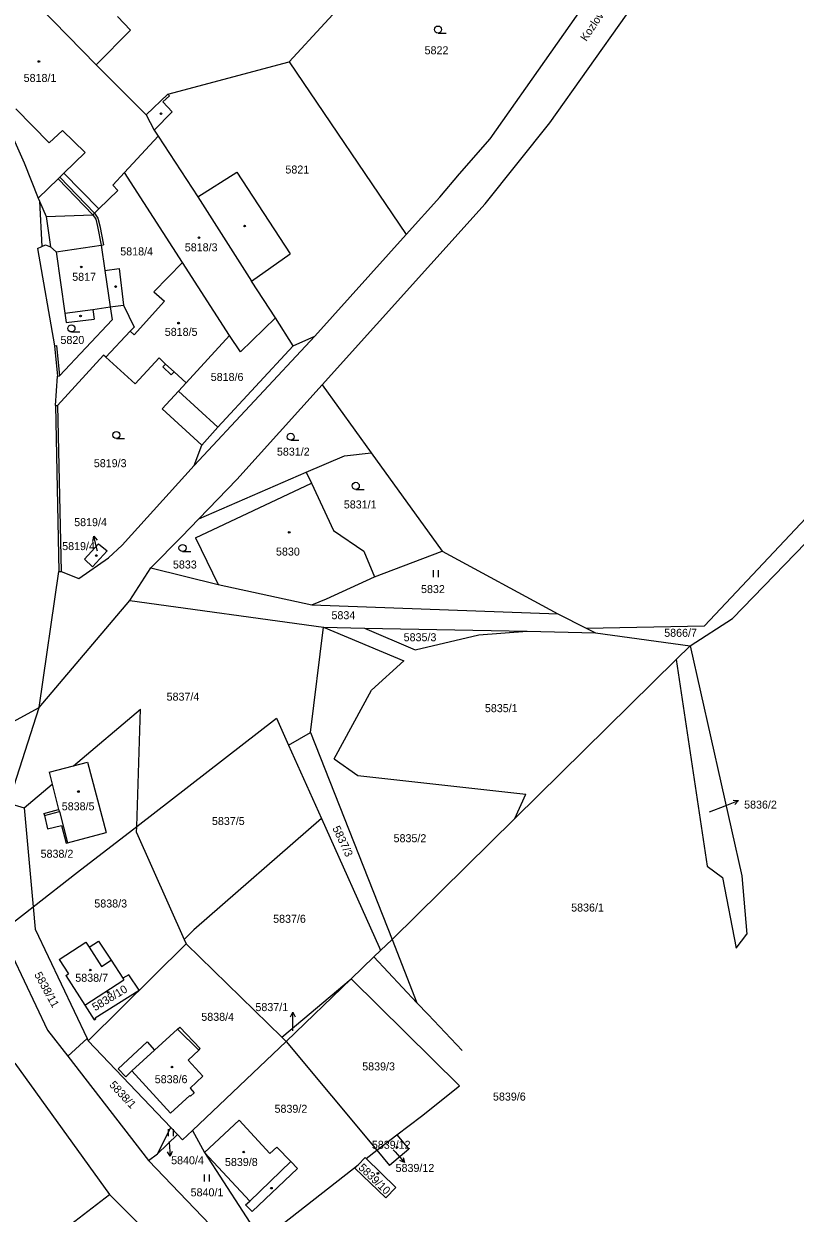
# Model space of a CAD drawing. Extents: x -717507 to -715515, y -957700 to -954941.
# Drawn here: x -715850.3 to -715686.5, y -955475.1 to -955222.4 of the extents above; entities that cross this region are included whole.
import ezdxf

# ---------------------------------------------------------------- set-up
doc = ezdxf.new("R2010")
doc.units = 0
for name, color, linetype in [('Hranice parcel', 7, 'Continuous'), ('Parcelní čísla', 7, 'Continuous'), ('Pop  PČ popisy', 7, 'Continuous'), ('Vnitřní kresba', 7, 'Continuous'), ('Značky budov', 7, 'Continuous'), ('Značky kultur', 7, 'Continuous')]:
    doc.layers.add(name, color=color, linetype=linetype)

msp = doc.modelspace()

# ---------------------------------------------------------------- linework, layer by layer
at = {"layer": 'Hranice parcel'}
for points in [[(-715738.6, -955243.39), (-715665.35, -955140.11)], [(-715793.97, -955230.46), (-715771.23, -955205.7)], [(-715751.32, -955246.77), (-715725.4, -955209.9)], [(-715853.12, -955212.39), (-715834.93, -955231.09)], [(-715834.93, -955231.09), (-715824.34, -955241.7)], [(-715819.71, -955237.33), (-715793.97, -955230.46)], [(-715793.97, -955230.46), (-715769.13, -955267.15)], [(-715824.34, -955241.7), (-715819.71, -955237.33)], [(-715820.8, -955238.95), (-715819.42, -955237.64)], [(-715819.71, -955237.33), (-715819.42, -955237.64)], [(-715822.63, -955244.95), (-715818.85, -955241.07)], [(-715820.8, -955238.95), (-715818.85, -955241.07)], [(-715854.51, -955242.32), (-715850.25, -955251.87)], [(-715752.32, -955260.58), (-715738.6, -955243.39)], [(-715828.97, -955253.97), (-715821.78, -955246.26)], [(-715822.63, -955244.95), (-715821.78, -955246.26)], [(-715821.78, -955246.26), (-715813.38, -955259.14)], [(-715757.78, -955254.24), (-715751.32, -955246.77)], [(-715850.25, -955251.87), (-715847.25, -955259.39)], [(-715831.45, -955256.63), (-715828.97, -955253.97)], [(-715816.61, -955273.07), (-715828.97, -955253.97)], [(-715813.38, -955259.14), (-715805.11, -955253.86)], [(-715805.11, -955253.86), (-715793.78, -955271.22)], [(-715847.25, -955259.39), (-715843.02, -955255.3)], [(-715843.02, -955255.3), (-715835.67, -955262.95)], [(-715761.99, -955259.2), (-715757.78, -955254.24)], [(-715834.39, -955261.7), (-715830.35, -955257.75)], [(-715831.45, -955256.63), (-715830.35, -955257.75)], [(-715847.25, -955259.39), (-715846.96, -955260.05)], [(-715846.96, -955260.05), (-715846.52, -955269.68)], [(-715787, -955299.06), (-715752.32, -955260.58)], [(-715769.13, -955267.15), (-715761.99, -955259.2)], [(-715835.67, -955262.95), (-715835.31, -955262.6)], [(-715835.31, -955262.6), (-715834.39, -955261.7)], [(-715788.52, -955288.71), (-715769.13, -955267.15)], [(-715847.44, -955270.13), (-715846.52, -955269.68)], [(-715847.44, -955270.13), (-715843.8, -955290.75)], [(-715846.52, -955269.68), (-715845.75, -955269.3)], [(-715845.75, -955269.3), (-715844.68, -955269.74)], [(-715844.68, -955269.74), (-715843.48, -955270.81)], [(-715843.48, -955270.81), (-715833.89, -955269.41)], [(-715843.48, -955270.81), (-715841.61, -955283.86)], [(-715833.89, -955269.41), (-715833.11, -955274.78)], [(-715801.94, -955277.03), (-715793.78, -955271.22)], [(-715816.61, -955273.07), (-715822.7, -955279.34)], [(-715806.62, -955288.55), (-715816.61, -955273.07)], [(-715833.11, -955274.78), (-715830.08, -955274.36)], [(-715830.08, -955274.36), (-715829.15, -955282.12)], [(-715796.91, -955284.85), (-715801.94, -955277.03)], [(-715820.45, -955281.3), (-715826.89, -955288.42)], [(-715822.7, -955279.34), (-715820.45, -955281.3)], [(-715841.61, -955283.86), (-715841.33, -955285.83)], [(-715835.68, -955283.03), (-715831.99, -955282.52)], [(-715835.68, -955283.03), (-715835.39, -955285.11)], [(-715831.99, -955282.52), (-715831.59, -955285.23)], [(-715829.15, -955282.12), (-715826.92, -955286.8)], [(-715842.73, -955297.17), (-715831.59, -955285.23)], [(-715841.33, -955285.83), (-715835.39, -955285.11)], [(-715827.72, -955287.65), (-715826.92, -955286.8)], [(-715796.91, -955284.85), (-715804.34, -955292.08)], [(-715793.11, -955290.76), (-715796.91, -955284.85)], [(-715832.94, -955293.16), (-715827.72, -955287.65)], [(-715826.89, -955288.42), (-715827.72, -955287.65)], [(-715806.62, -955288.55), (-715815.86, -955298.65)], [(-715814.15, -955316.23), (-715788.52, -955288.71)], [(-715804.34, -955292.08), (-715806.62, -955288.55)], [(-715793.11, -955290.76), (-715788.52, -955288.71)], [(-715843.8, -955290.75), (-715843.19, -955297.21)], [(-715843.16, -955303.47), (-715833.37, -955292.76)], [(-715832.94, -955293.16), (-715833.37, -955292.76)], [(-715826.67, -955298.86), (-715832.94, -955293.16)], [(-715826.67, -955298.86), (-715821.61, -955293.36)], [(-715821.61, -955293.36), (-715820.22, -955294.64)], [(-715820.79, -955295.27), (-715820.22, -955294.64)], [(-715820.79, -955295.27), (-715819.01, -955296.91)], [(-715819.01, -955296.91), (-715818.43, -955296.28)], [(-715818.43, -955296.28), (-715815.86, -955298.65)], [(-715705.8, -955350.3), (-715654.8, -955296.1)], [(-715843.61, -955303.48), (-715843.19, -955297.21)], [(-715843.19, -955297.21), (-715842.73, -955297.17)], [(-715817.47, -955300.4), (-715815.86, -955298.65)], [(-715805.11, -955319.15), (-715787, -955299.06)], [(-715787, -955299.06), (-715776.55, -955313.53)], [(-715820.93, -955304.17), (-715817.47, -955300.4)], [(-715843.61, -955303.48), (-715843.16, -955303.47)], [(-715843.61, -955303.48), (-715842.87, -955338.72)], [(-715820.93, -955304.17), (-715812.55, -955311.91)], [(-715699.86, -955348.7), (-715657.74, -955305.22)], [(-715814.15, -955316.23), (-715812.55, -955311.91)], [(-715790.34, -955317.64), (-715782.25, -955314.14)], [(-715782.25, -955314.14), (-715776.55, -955313.53)], [(-715776.55, -955313.53), (-715761.46, -955334.42)], [(-715829.47, -955333.13), (-715814.15, -955316.23)], [(-715813.15, -955327.52), (-715790.34, -955317.64)], [(-715813.15, -955327.52), (-715805.11, -955319.15)], [(-715790.34, -955317.64), (-715789.24, -955319.98)], [(-715813.85, -955331.54), (-715789.24, -955319.98)], [(-715789.24, -955319.98), (-715784.53, -955329.99)], [(-715816.82, -955331.34), (-715813.15, -955327.52)], [(-715823.38, -955337.96), (-715816.82, -955331.34)], [(-715813.85, -955331.54), (-715809.07, -955341.5)], [(-715784.53, -955329.99), (-715778.09, -955334.43)], [(-715837.42, -955336.07), (-715834.44, -955332.87), (-715832.63, -955334.34), (-715835.71, -955337.71), (-715837.42, -955336.07)], [(-715832.32, -955335.84), (-715829.47, -955333.13)], [(-715778.09, -955334.43), (-715775.84, -955339.87)], [(-715775.84, -955339.87), (-715761.46, -955334.42)], [(-715761.46, -955334.42), (-715736.9, -955347.72)], [(-715838.65, -955340.22), (-715832.32, -955335.84)], [(-715847.04, -955367.61), (-715842.87, -955338.72)], [(-715842.87, -955338.72), (-715842.42, -955338.71)], [(-715842.42, -955338.71), (-715838.65, -955340.22)], [(-715827.79, -955344.89), (-715823.38, -955337.96)], [(-715823.38, -955337.96), (-715809.07, -955341.5)], [(-715786.05, -955344.52), (-715775.84, -955339.87)], [(-715809.07, -955341.5), (-715789.19, -955345.81)], [(-715847.04, -955367.61), (-715827.79, -955344.89)], [(-715827.79, -955344.89), (-715786.66, -955350.55)], [(-715789.19, -955345.81), (-715786.05, -955344.52)], [(-715789.19, -955345.81), (-715736.9, -955347.72)], [(-715736.9, -955347.72), (-715730.91, -955350.73)], [(-715708.83, -955354.55), (-715699.86, -955348.7)], [(-715789.45, -955372.95), (-715786.66, -955350.55)], [(-715786.66, -955350.55), (-715777.96, -955350.73)], [(-715786.66, -955350.55), (-715769.65, -955357.7)], [(-715777.96, -955350.73), (-715767.25, -955355.35)], [(-715777.96, -955350.73), (-715743.42, -955351.43)], [(-715767.25, -955355.35), (-715753.69, -955352.17)], [(-715753.69, -955352.17), (-715743.42, -955351.43)], [(-715743.42, -955351.43), (-715728.93, -955351.73)], [(-715730.91, -955350.73), (-715705.8, -955350.3)], [(-715730.91, -955350.73), (-715728.93, -955351.73)], [(-715728.93, -955351.73), (-715708.83, -955354.55)], [(-715711.76, -955357.44), (-715708.83, -955354.55)], [(-715708.83, -955354.55), (-715697.87, -955403.39)], [(-715746.04, -955391.2), (-715711.76, -955357.44)], [(-715711.76, -955357.44), (-715705.22, -955401.33)], [(-715776.46, -955363.95), (-715769.65, -955357.7)], [(-715784.44, -955378.55), (-715776.46, -955363.95)], [(-715864.69, -955377.18), (-715847.04, -955367.61)], [(-715853.56, -955387.91), (-715847.04, -955367.61)], [(-715839.78, -955380.04), (-715825.55, -955368)], [(-715826.33, -955392.87), (-715825.55, -955368)], [(-715826.33, -955392.87), (-715796.68, -955369.86)], [(-715796.68, -955369.86), (-715794.1, -955375.62)], [(-715794.1, -955375.62), (-715789.45, -955372.95)], [(-715789.45, -955372.95), (-715772.12, -955416.88)], [(-715794.1, -955375.62), (-715787.11, -955391.19)], [(-715844.94, -955381.39), (-715839.78, -955380.04)], [(-715839.78, -955380.04), (-715836.77, -955379.25)], [(-715836.77, -955379.25), (-715832.81, -955394.21)], [(-715784.44, -955378.55), (-715779.39, -955382.1)], [(-715844.94, -955381.39), (-715844.31, -955383.88)], [(-715779.39, -955382.1), (-715743.74, -955386.05)], [(-715850.25, -955388.9), (-715844.31, -955383.88)], [(-715844.31, -955383.88), (-715842.95, -955389.27)], [(-715853.56, -955387.91), (-715850.25, -955388.9)], [(-715746.04, -955391.2), (-715743.74, -955386.05)], [(-715850.25, -955388.9), (-715848.33, -955409.96)], [(-715846.05, -955390.14), (-715842.95, -955389.27)], [(-715846.05, -955390.14), (-715845.94, -955390.59)], [(-715845.94, -955390.59), (-715845.28, -955393.39)], [(-715845.28, -955393.39), (-715842.31, -955392.69)], [(-715842.31, -955392.69), (-715841.34, -955396.45)], [(-715838.9, -955402.62), (-715826.33, -955392.87)], [(-715826.37, -955394.17), (-715826.33, -955392.87)], [(-715787.11, -955391.19), (-715814.24, -955414.84)], [(-715787.11, -955391.19), (-715774.88, -955418.55)], [(-715772.12, -955416.88), (-715746.04, -955391.2)], [(-715841.03, -955396.35), (-715832.81, -955394.21)], [(-715826.37, -955394.17), (-715816.26, -955416.93)], [(-715841.34, -955396.45), (-715841.03, -955396.35)], [(-715848.33, -955409.96), (-715838.9, -955402.62)], [(-715705.22, -955401.33), (-715701.92, -955403.77)], [(-715701.92, -955403.77), (-715699.08, -955418.73)], [(-715697.87, -955403.39), (-715696.81, -955415.75)], [(-715853.5, -955413.99), (-715848.33, -955409.96)], [(-715848.33, -955409.96), (-715847.9, -955414.7)], [(-715847.9, -955414.7), (-715836.9, -955437.95)], [(-715814.24, -955414.84), (-715816.26, -955416.93)], [(-715842.79, -955421.18), (-715837.18, -955417.48)], [(-715837.18, -955417.48), (-715836.48, -955418.55)], [(-715836.67, -955438.44), (-715815.86, -955417.83)], [(-715836.48, -955418.55), (-715834.43, -955417.23)], [(-715834.43, -955417.23), (-715831.78, -955421.33)], [(-715816.26, -955416.93), (-715815.86, -955417.83)], [(-715815.86, -955417.83), (-715795.53, -955437.64)], [(-715774.58, -955419.24), (-715772.12, -955416.88)], [(-715699.08, -955418.73), (-715696.81, -955415.75)], [(-715852.73, -955420.44), (-715845.27, -955436.19)], [(-715780.84, -955425.27), (-715775.98, -955420.59)], [(-715775.98, -955420.59), (-715774.58, -955419.24)], [(-715775.98, -955420.59), (-715766.86, -955430.39)], [(-715774.88, -955418.55), (-715774.58, -955419.24)], [(-715842.79, -955421.18), (-715840.82, -955424.17)], [(-715831.78, -955421.33), (-715829.33, -955425.11)], [(-715841.42, -955424.55), (-715840.82, -955424.17)], [(-715841.42, -955424.55), (-715837.4, -955430.88)], [(-715837.4, -955430.88), (-715829.08, -955425.5)], [(-715828.01, -955424.4), (-715829.33, -955425.11)], [(-715829.33, -955425.11), (-715829.08, -955425.5)], [(-715825.84, -955427.68), (-715828.01, -955424.4)], [(-715795.53, -955437.64), (-715780.84, -955425.27)], [(-715794.6, -955438.55), (-715780.84, -955425.27)], [(-715780.84, -955425.27), (-715757.81, -955447.99)], [(-715835.19, -955433.58), (-715825.84, -955427.68)], [(-715837.4, -955430.88), (-715835.38, -955433.99)], [(-715766.86, -955430.39), (-715764.47, -955432.85)], [(-715764.47, -955432.85), (-715757.23, -955440.47)], [(-715835.38, -955433.99), (-715835.06, -955433.78)], [(-715835.06, -955433.78), (-715835.19, -955433.58)], [(-715822.58, -955440.42), (-715817.67, -955435.93)], [(-715817.67, -955435.93), (-715817.22, -955435.56)], [(-715817.22, -955435.56), (-715812.86, -955440.05)], [(-715845.27, -955436.19), (-715840.99, -955441.71)], [(-715840.99, -955441.71), (-715836.9, -955437.95)], [(-715836.9, -955437.95), (-715836.67, -955438.44)], [(-715836.67, -955438.44), (-715819.07, -955456.86)], [(-715795.53, -955437.64), (-715794.6, -955438.55)], [(-715830.27, -955444.39), (-715824.16, -955438.68)], [(-715824.16, -955438.68), (-715822.58, -955440.42)], [(-715815.45, -955442.52), (-715813.16, -955440.41)], [(-715814.53, -955457.48), (-715794.6, -955438.55)], [(-715813.16, -955440.41), (-715812.86, -955440.05)], [(-715794.6, -955438.55), (-715775.38, -955461.67)], [(-715852.21, -955443.2), (-715832.1, -955471.05)], [(-715840.99, -955441.71), (-715823.82, -955463.87)], [(-715815.45, -955442.52), (-715812.28, -955445.97)], [(-715830.27, -955444.39), (-715828.69, -955446.08)], [(-715828.69, -955446.08), (-715827.39, -955444.8)], [(-715827.39, -955444.8), (-715819.16, -955453.81)], [(-715815.02, -955448.49), (-715812.28, -955445.97)], [(-715815.02, -955448.49), (-715814.14, -955449.45)], [(-715765.89, -955454.42), (-715757.81, -955447.99)], [(-715819.16, -955453.81), (-715815.08, -955450.05)], [(-715815.08, -955450.05), (-715814.95, -955450.2)], [(-715814.95, -955450.2), (-715814.14, -955449.45)], [(-715811.97, -955462.17), (-715804.57, -955455.26)], [(-715804.57, -955455.26), (-715798.06, -955462.39)], [(-715771.13, -955458.42), (-715765.89, -955454.42)], [(-715821.91, -955462.45), (-715819.07, -955456.86)], [(-715821.91, -955462.45), (-715817.69, -955458.31)], [(-715819.07, -955456.86), (-715817.69, -955458.31)], [(-715817.69, -955458.31), (-715816.6, -955459.45)], [(-715816.6, -955459.45), (-715814.53, -955457.48)], [(-715814.53, -955457.48), (-715811.97, -955462.17)], [(-715775.38, -955461.67), (-715771.13, -955458.42)], [(-715771.13, -955458.42), (-715768.57, -955461.46), (-715772.65, -955464.9)], [(-715798.06, -955462.39), (-715796.62, -955461)], [(-715796.62, -955461), (-715793.64, -955464.1)], [(-715823.82, -955463.87), (-715821.91, -955462.45)], [(-715811.97, -955462.17), (-715802.36, -955472.48)], [(-715811.97, -955462.17), (-715799.84, -955480.85)], [(-715779.3, -955464.75), (-715777.86, -955463.25)], [(-715777.86, -955463.25), (-715777.65, -955463.45)], [(-715777.65, -955463.45), (-715775.38, -955461.67)], [(-715777.65, -955463.45), (-715771.33, -955469.57)], [(-715775.38, -955461.67), (-715772.65, -955464.9)], [(-715823.82, -955463.87), (-715794.5, -955494.51)], [(-715801.82, -955474.72), (-715792.23, -955465.57)], [(-715799.84, -955480.85), (-715779.3, -955464.75)], [(-715793.64, -955464.1), (-715792.23, -955465.57)], [(-715780.01, -955465.48), (-715779.3, -955464.75)], [(-715780.01, -955465.48), (-715773.44, -955471.79)], [(-715843.19, -955479.58), (-715832.1, -955471.05)], [(-715832.1, -955471.05), (-715808.03, -955495.19)], [(-715773.44, -955471.79), (-715771.33, -955469.57)], [(-715803.22, -955473.28), (-715802.36, -955472.48)], [(-715803.22, -955473.28), (-715801.82, -955474.72)]]:
    msp.add_lwpolyline(points, dxfattribs=at)
at = {"layer": 'Pop  PČ popisy'}
for points in [[(-715835.7, -955332.34), (-715835.46, -955331.25), (-715834.73, -955332.1)], [(-715834.73, -955334.16), (-715835.46, -955331.25)], [(-715834.67, -955334.38), (-715834.73, -955334.16)], [(-715701.36, -955388.48), (-715698.56, -955387.4)], [(-715699.67, -955387.29), (-715698.56, -955387.4), (-715699.31, -955388.23)], [(-715704.71, -955389.78), (-715701.36, -955388.48)], [(-715793.67, -955433.32), (-715793.17, -955432.32), (-715792.67, -955433.32)], [(-715793.17, -955435.32), (-715793.17, -955432.32)], [(-715793.17, -955436.31), (-715793.17, -955435.32)], [(-715819.49, -955459.8), (-715819.48, -955459.97)], [(-715819.48, -955459.97), (-715819.24, -955462.96)], [(-715818.82, -955461.92), (-715819.24, -955462.96), (-715819.82, -955462)], [(-715771.91, -955461.57), (-715771.47, -955462.05)], [(-715771.47, -955462.05), (-715769.46, -955464.28)], [(-715769.76, -955463.2), (-715769.46, -955464.28), (-715770.5, -955463.87)]]:
    msp.add_lwpolyline(points, dxfattribs=at)
at = {"layer": 'Vnitřní kresba'}
for points in [[(-715830.46, -955220.81), (-715827.68, -955223.71)], [(-715834.93, -955231.09), (-715827.68, -955223.71)], [(-715852, -955240.42), (-715844.94, -955247.68)], [(-715824.34, -955241.7), (-715822.63, -955244.95)], [(-715844.94, -955247.68), (-715842.14, -955245.01)], [(-715842.14, -955245.01), (-715837.31, -955249.74)], [(-715841.8, -955254.11), (-715837.31, -955249.74)], [(-715843.02, -955255.3), (-715842.67, -955254.98)], [(-715842.67, -955254.98), (-715841.8, -955254.11)], [(-715842.67, -955254.98), (-715835.31, -955262.6)], [(-715841.8, -955254.11), (-715834.39, -955261.7)], [(-715846.96, -955260.05), (-715845.6, -955263.32)], [(-715813.38, -955259.14), (-715801.94, -955277.03)], [(-715845.6, -955263.32), (-715835.67, -955262.95)], [(-715845.6, -955263.32), (-715844.68, -955269.74)], [(-715835.67, -955262.95), (-715835.05, -955263.85)], [(-715835.31, -955262.6), (-715834.6, -955263.65)], [(-715835.05, -955263.85), (-715834.65, -955265.42)], [(-715834.6, -955263.65), (-715834.16, -955265.31)], [(-715834.65, -955265.42), (-715833.89, -955269.41)], [(-715834.16, -955265.31), (-715833.39, -955269.34)], [(-715833.89, -955269.41), (-715833.39, -955269.34)], [(-715833.11, -955274.78), (-715831.99, -955282.52)], [(-715841.61, -955283.86), (-715835.68, -955283.03)], [(-715831.99, -955282.52), (-715829.15, -955282.12)], [(-715843.8, -955290.75), (-715843.35, -955290.7)], [(-715843.35, -955290.7), (-715842.73, -955297.17)], [(-715809.09, -955308.09), (-715793.11, -955290.76)], [(-715820.22, -955294.64), (-715818.43, -955296.28)], [(-715817.47, -955300.4), (-715809.09, -955308.09)], [(-715843.16, -955303.47), (-715842.42, -955338.71)], [(-715812.55, -955311.91), (-715809.09, -955308.09)], [(-715845.94, -955390.59), (-715842.77, -955389.7)], [(-715842.95, -955389.27), (-715842.77, -955389.7)], [(-715842.77, -955389.7), (-715841.03, -955396.35)], [(-715772.12, -955416.88), (-715766.86, -955430.39)], [(-715836.48, -955418.55), (-715833.83, -955422.66)], [(-715833.83, -955422.66), (-715831.78, -955421.33)], [(-715817.67, -955435.93), (-715813.16, -955440.41)], [(-715827.39, -955444.8), (-715822.58, -955440.42)], [(-715802.36, -955472.48), (-715793.64, -955464.1)]]:
    msp.add_lwpolyline(points, dxfattribs=at)
at = {"layer": 'Značky budov'}
for centre in [(-715847.13, -955230.37), (-715821.18, -955241.47), (-715803.43, -955265.33), (-715813.13, -955267.81), (-715838.12, -955274.03), (-715830.82, -955278.19), (-715838.27, -955284.44), (-715817.47, -955285.96), (-715793.96, -955330.4), (-715834.94, -955335.33), (-715838.72, -955385.48), (-715836.21, -955423.4), (-715832.41, -955428.12), (-715818.87, -955444), (-715771.07, -955461.08), (-715803.63, -955462.07), (-715775.13, -955466.62), (-715797.74, -955469.74)]:
    msp.add_circle(centre, 0.175, dxfattribs=at)
at = {"layer": 'Značky kultur'}
for points in [[(-715762.36, -955224.33), (-715760.61, -955224.33)], [(-715840.21, -955287.84), (-715838.46, -955287.84)], [(-715830.67, -955310.48), (-715828.92, -955310.48)], [(-715793.64, -955310.84), (-715791.89, -955310.84)], [(-715779.83, -955321.28), (-715778.08, -955321.28)], [(-715816.62, -955334.48), (-715814.87, -955334.48)], [(-715763.33, -955339.92), (-715763.33, -955338.42)], [(-715762.29, -955339.92), (-715762.29, -955338.42)], [(-715819.57, -955458.72), (-715819.57, -955457.22)], [(-715818.53, -955458.72), (-715818.53, -955457.22)], [(-715811.93, -955468.33), (-715811.93, -955466.83)], [(-715810.89, -955468.33), (-715810.89, -955466.83)]]:
    msp.add_lwpolyline(points, dxfattribs=at)
for centre in [(-715762.36, -955223.58), (-715840.21, -955287.09), (-715830.67, -955309.73), (-715793.64, -955310.09), (-715779.83, -955320.53), (-715816.62, -955333.73)]:
    msp.add_circle(centre, 0.75, dxfattribs=at)

# ---------------------------------------------------------------- texts
at = {"layer": 'Parcelní čísla'}
for s, p in [('5822', (-715765.21, -955228.84)), ('5818/1', (-715850.36, -955234.71)), ('5821', (-715794.77, -955254.17)), ('5818/3', (-715816.14, -955270.7)), ('5818/4', (-715829.84, -955271.57)), ('5817', (-715840.05, -955276.97)), ('5820', (-715842.54, -955290.38)), ('5818/5', (-715820.39, -955288.66)), ('5818/6', (-715810.63, -955298.24)), ('5831/2', (-715796.57, -955314.11)), ('5819/3', (-715835.46, -955316.56)), ('5831/1', (-715782.37, -955325.33)), ('5819/4', (-715839.63, -955329.09)), ('5819/4', (-715842.18, -955334.18)), ('5830', (-715796.77, -955335.34)), ('5833', (-715818.66, -955338.09)), ('5832', (-715765.97, -955343.31)), ('5834', (-715784.99, -955348.86)), ('5835/3', (-715769.66, -955353.54)), ('5866/7', (-715714.33, -955352.6)), ('5837/4', (-715820, -955366.16)), ('5835/1', (-715752.41, -955368.61)), ('5838/5', (-715842.27, -955389.46)), ('5836/2', (-715697.36, -955389.1)), ('5837/5', (-715810.37, -955392.58)), ('5835/2', (-715771.8, -955396.24)), ('5838/2', (-715846.76, -955399.54)), ('5838/3', (-715835.35, -955410.11)), ('5836/1', (-715734.09, -955410.97)), ('5837/6', (-715797.38, -955413.36)), ('5838/7', (-715839.39, -955425.89)), ('5837/1', (-715801.14, -955432.12)), ('5838/4', (-715812.63, -955434.19)), ('5839/3', (-715778.46, -955444.72)), ('5838/6', (-715822.52, -955447.44)), ('5839/6', (-715750.69, -955451.13)), ('5839/2', (-715797.08, -955453.72)), ('5839/12', (-715776.41, -955461.37)), ('5840/4', (-715819.04, -955464.66)), ('5839/8', (-715807.61, -955465.03)), ('5839/12', (-715771.37, -955466.29)), ('5840/1', (-715814.9, -955471.48))]:
    msp.add_text(s, height=1.7, dxfattribs=at).set_placement(p)
for s, rotation, p in [('5837/3', 295.2023, (-715784.84, -955393.24)), ('5838/11', 298.8024, (-715848.16, -955424.36)), ('5838/10', 31.1002, (-715835.18, -955432.17)), ('5838/1', 313.1025, (-715832.3, -955447.91)), ('5839/10', 316.2025, (-715779.4, -955465.54))]:
    msp.add_text(s, height=1.7, rotation=rotation, dxfattribs=at).set_placement(p)
at = {"layer": 'Pop  PČ popisy'}
msp.add_text('Kozlova', height=1.7, rotation=56.1004, dxfattribs=at).set_placement((-715730.87, -955226.22))

doc.saveas('drawing.dxf')
